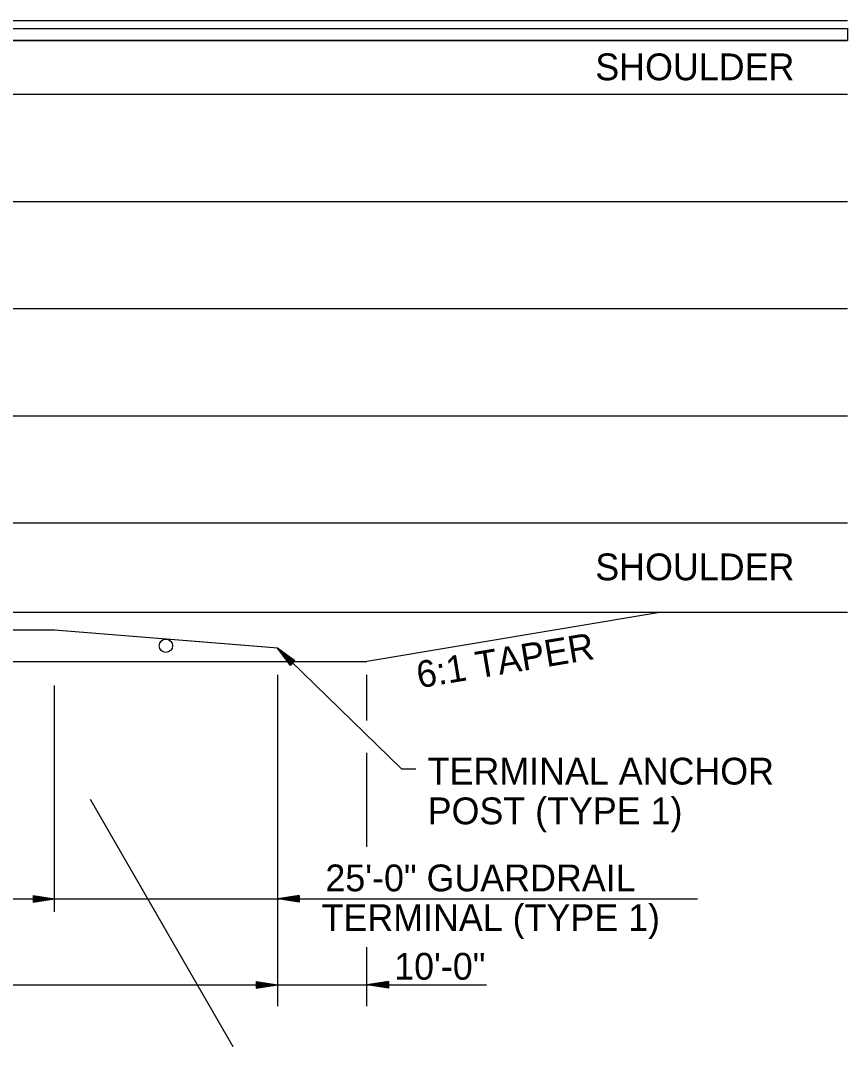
# Model space of a CAD drawing. Extents: x 1373853 to 1374003, y 380191 to 380927.
# Drawn here: x 1373952.42 to 1373970.94, y 380716.96 to 380739.93 of the extents above; entities that cross this region are included whole.
import ezdxf

# ---------------------------------------------------------------- set-up
doc = ezdxf.new("R2010")
doc.units = 0
for name, color, linetype in [('2', 7, 'Continuous'), ('44', 7, 'Continuous'), ('7', 7, 'Continuous'), ('E_Existing ROW', 7, 'Continuous'), ('R_Draft', 7, 'Continuous'), ('R_Proposed Road', 7, 'Continuous')]:
    doc.layers.add(name, color=color, linetype=linetype)

msp = doc.modelspace()

# ---------------------------------------------------------------- linework, layer by layer
at = {"layer": '2'}
for p, q in [((1373958.168, 380725.874), (1373960.948, 380723.17)), ((1373958.176, 380717.856), (1373958.176, 380725.281)), ((1373960.176, 380724.258), (1373960.176, 380725.281)), ((1373953.176, 380719.97), (1373953.176, 380725.038)), ((1373960.176, 380721.429), (1373960.176, 380723.533)), ((1373960.948, 380723.17), (1373961.267, 380723.17)), ((1373903.176, 380720.26), (1373967.577, 380720.26)), ((1373960.176, 380717.856), (1373960.176, 380719.184)), ((1373888.057, 380718.335), (1373962.85, 380718.335))]:
    msp.add_line(p, q, dxfattribs=at)
at = {"layer": '44'}
msp.add_line((1373877.32, 380726.678), (1373970.938, 380726.678), dxfattribs=at)
at = {"layer": '7'}
for p, q in [((1373958.563, 380725.591), (1373958.168, 380725.874)), ((1373958.463, 380725.49), (1373958.168, 380725.874)), ((1373958.556, 380725.585), (1373958.227, 380725.82)), ((1373958.473, 380725.497), (1373958.227, 380725.82)), ((1373958.483, 380725.508), (1373958.287, 380725.761)), ((1373958.545, 380725.576), (1373958.287, 380725.761)), ((1373958.538, 380725.567), (1373958.344, 380725.706)), ((1373958.489, 380725.517), (1373958.344, 380725.706)), ((1373958.496, 380725.524), (1373958.4, 380725.65)), ((1373958.527, 380725.558), (1373958.4, 380725.65)), ((1373958.504, 380725.533), (1373958.46, 380725.593)), ((1373958.522, 380725.546), (1373958.46, 380725.593)), ((1373958.563, 380725.591), (1373958.463, 380725.49)), ((1373952.696, 380720.334), (1373953.176, 380720.26)), ((1373952.696, 380720.334), (1373952.696, 380720.188)), ((1373952.696, 380720.319), (1373953.094, 380720.26)), ((1373952.696, 380720.307), (1373953.013, 380720.26)), ((1373952.696, 380720.295), (1373952.932, 380720.26)), ((1373952.696, 380720.283), (1373952.853, 380720.26)), ((1373952.696, 380720.272), (1373952.772, 380720.26)), ((1373952.696, 380720.188), (1373953.176, 380720.26)), ((1373952.696, 380720.238), (1373952.853, 380720.26)), ((1373952.696, 380720.214), (1373953.013, 380720.26)), ((1373952.696, 380720.2), (1373953.094, 380720.26)), ((1373952.696, 380720.224), (1373952.932, 380720.26)), ((1373952.696, 380720.25), (1373952.772, 380720.26)), ((1373958.656, 380720.334), (1373958.176, 380720.26)), ((1373958.656, 380720.188), (1373958.176, 380720.26)), ((1373958.656, 380720.319), (1373958.257, 380720.26)), ((1373958.656, 380720.2), (1373958.257, 380720.26)), ((1373958.656, 380720.307), (1373958.338, 380720.26)), ((1373958.656, 380720.214), (1373958.338, 380720.26)), ((1373958.656, 380720.295), (1373958.419, 380720.26)), ((1373958.656, 380720.224), (1373958.419, 380720.26)), ((1373958.656, 380720.283), (1373958.498, 380720.26)), ((1373958.656, 380720.238), (1373958.498, 380720.26)), ((1373958.656, 380720.272), (1373958.579, 380720.26)), ((1373958.656, 380720.25), (1373958.579, 380720.26)), ((1373958.656, 380720.334), (1373958.656, 380720.188)), ((1373957.696, 380718.409), (1373958.176, 380718.335)), ((1373957.696, 380718.409), (1373957.696, 380718.264)), ((1373957.696, 380718.395), (1373958.094, 380718.335)), ((1373957.696, 380718.383), (1373958.013, 380718.335)), ((1373957.696, 380718.371), (1373957.932, 380718.335)), ((1373957.696, 380718.359), (1373957.853, 380718.335)), ((1373957.696, 380718.347), (1373957.772, 380718.335)), ((1373957.696, 380718.264), (1373958.176, 380718.335)), ((1373957.696, 380718.314), (1373957.853, 380718.335)), ((1373957.696, 380718.29), (1373958.013, 380718.335)), ((1373957.696, 380718.275), (1373958.094, 380718.335)), ((1373957.696, 380718.299), (1373957.932, 380718.335)), ((1373957.696, 380718.326), (1373957.772, 380718.335)), ((1373960.656, 380718.409), (1373960.176, 380718.335)), ((1373960.656, 380718.264), (1373960.176, 380718.335)), ((1373960.656, 380718.395), (1373960.257, 380718.335)), ((1373960.656, 380718.275), (1373960.257, 380718.335)), ((1373960.656, 380718.383), (1373960.338, 380718.335)), ((1373960.656, 380718.29), (1373960.338, 380718.335)), ((1373960.656, 380718.371), (1373960.419, 380718.335)), ((1373960.656, 380718.299), (1373960.419, 380718.335)), ((1373960.656, 380718.359), (1373960.498, 380718.335)), ((1373960.656, 380718.314), (1373960.498, 380718.335)), ((1373960.656, 380718.347), (1373960.579, 380718.335)), ((1373960.656, 380718.326), (1373960.579, 380718.335)), ((1373960.656, 380718.409), (1373960.656, 380718.264))]:
    msp.add_line(p, q, dxfattribs=at)
at = {"layer": 'E_Existing ROW'}
msp.add_lwpolyline([(1373953.976, 380722.493), (1373957.172, 380716.957)], dxfattribs=at)
at = {"layer": 'R_Draft'}
msp.add_lwpolyline([(1373877.32, 380739.748), (1373970.938, 380739.748), (1373970.938, 380739.478), (1373877.32, 380739.478)], close=True, dxfattribs=at)
at = {"layer": 'R_Proposed Road'}
for p, q in [((1373877.32, 380739.928), (1373970.938, 380739.928)), ((1373877.32, 380739.748), (1373970.938, 380739.748)), ((1373877.32, 380739.478), (1373970.938, 380739.478)), ((1373877.32, 380738.278), (1373970.938, 380738.278)), ((1373877.32, 380735.878), (1373970.938, 380735.878)), ((1373877.32, 380733.478), (1373970.938, 380733.478)), ((1373877.32, 380731.078), (1373970.938, 380731.078)), ((1373877.32, 380728.678), (1373970.938, 380728.678)), ((1373966.776, 380726.678), (1373960.176, 380725.578))]:
    msp.add_line(p, q, dxfattribs=at)
for points in [[(1373958.176, 380725.878), (1373953.176, 380726.278), (1373940.692, 380726.278)], [(1373958.176, 380725.878), (1373955.684, 380726.078)], [(1373933.183, 380725.578), (1373960.176, 380725.578)]]:
    msp.add_lwpolyline(points, dxfattribs=at)
msp.add_circle((1373955.672, 380725.928), 0.15, dxfattribs=at)

# ---------------------------------------------------------------- texts
at = {"layer": '2'}
for s, rotation, p in [('SHOULDER', 0, (1373965.29, 380738.591)), ('SHOULDER', 0, (1373965.29, 380727.395)), ('6:1 TAPER', 9.4623, (1373961.339, 380724.975)), ('TERMINAL ANCHOR', 0, (1373961.535, 380722.822)), ('POST (TYPE 1)', 0, (1373961.535, 380721.932)), ('25\'-0" GUARDRAIL', 0, (1373959.244, 380720.431)), ('TERMINAL (TYPE 1)', 0, (1373959.159, 380719.541)), ('10\'-0"', 0, (1373960.785, 380718.452))]:
    msp.add_text(s, height=0.6, rotation=rotation, dxfattribs=at).set_placement(p)

doc.saveas('drawing.dxf')
